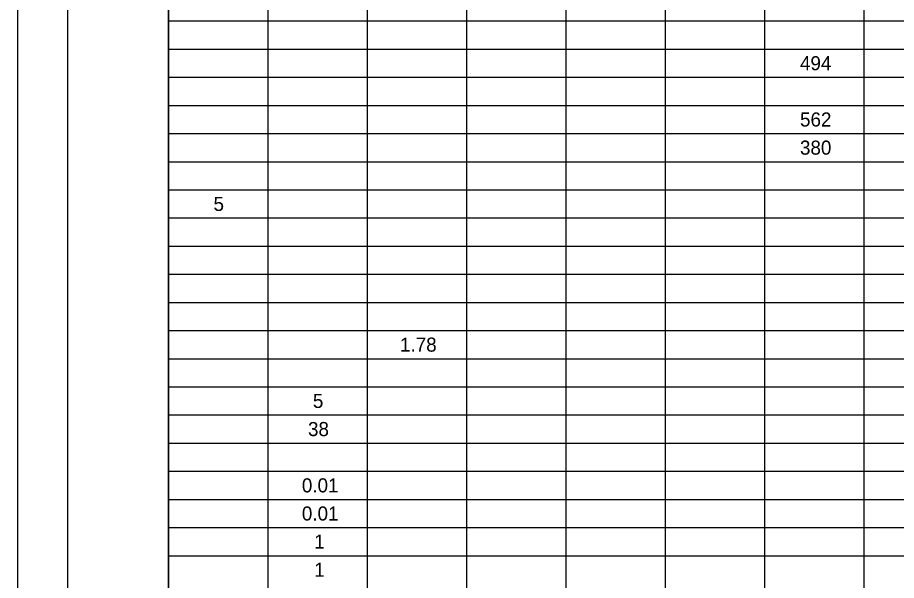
# Model space of a CAD drawing. Extents: x 0 to 34, y 0 to 22.
# Drawn here: x 0 to 8.74, y 10.89 to 16.49 of the extents above; entities that cross this region are included whole.
import ezdxf

# ---------------------------------------------------------------- set-up
doc = ezdxf.new("R2010")
doc.units = 0
for name, color, linetype in [('Default', 7, 'Continuous'), ('SH_Border', 7, 'Continuous'), ('SH_Cut_Line', 7, 'Continuous')]:
    doc.layers.add(name, color=color, linetype=linetype)

msp = doc.modelspace()

# ---------------------------------------------------------------- linework, layer by layer
at = {"layer": 'Default'}
for p, q in [((1.5, 21.5), (1.5, 0.50075)), ((2.4882, 20.94002), (2.4882, 0.50075)), ((3.4764, 20.94002), (3.4764, 0.50075)), ((4.4646, 20.94002), (4.4646, 0.50075)), ((5.4528, 20.94002), (5.4528, 0.50075)), ((6.441, 20.94002), (6.441, 0.50075)), ((7.4292, 20.94002), (7.4292, 0.50075)), ((8.4174, 20.94002), (8.4174, 0.50075)), ((1.5, 16.46018), (31.68951, 16.46018)), ((1.5, 16.18019), (31.68951, 16.18019)), ((1.5, 15.9002), (31.68951, 15.9002)), ((1.5, 15.62021), (31.68951, 15.62021)), ((1.5, 15.34022), (31.68951, 15.34022)), ((1.5, 15.06023), (31.68951, 15.06023)), ((1.5, 14.78024), (31.68951, 14.78024)), ((1.5, 14.50025), (31.68951, 14.50025)), ((1.5, 14.22026), (31.68951, 14.22026)), ((1.5, 13.94027), (31.68951, 13.94027)), ((1.5, 13.66028), (31.68951, 13.66028)), ((1.5, 13.38029), (31.68951, 13.38029)), ((1.5, 13.1003), (31.68951, 13.1003)), ((1.5, 12.82031), (31.68951, 12.82031)), ((1.5, 12.54032), (31.68951, 12.54032)), ((1.5, 12.26033), (31.68951, 12.26033)), ((1.5, 11.98034), (31.68951, 11.98034)), ((1.5, 11.70035), (31.68951, 11.70035)), ((1.5, 11.42036), (31.68951, 11.42036)), ((1.5, 11.14037), (31.68951, 11.14037))]:
    msp.add_line(p, q, dxfattribs=at)
at = {"layer": 'SH_Border'}
for points in [[(0.5, 21.5), (1.5, 21.5), (1.5, 0.5), (0.5, 0.5)], [(1.5, 21.5), (33.5, 21.5), (33.5, 0.5), (1.5, 0.5)]]:
    msp.add_lwpolyline(points, close=True, dxfattribs=at)
at = {"layer": 'SH_Cut_Line'}
msp.add_lwpolyline([(0, 0), (34, 0), (34, 22), (0, 22)], close=True, dxfattribs=at)

# ---------------------------------------------------------------- texts
at = {"layer": 'Default'}
for s, p in [('494', (7.780782, 15.970195)), ('562', (7.781166, 15.410215)), ('380', (7.780734, 15.130225)), ('5', (1.948675, 14.570245)), ('1.78', (3.803156, 13.170295)), ('5', (2.936875, 12.610315)), ('38', (2.888328, 12.330325)), ('0.01', (2.827249, 11.770345)), ('0.01', (2.827249, 11.490355)), ('1', (2.949552, 11.210365)), ('1', (2.949552, 10.930375))]:
    msp.add_text(s, height=0.14, dxfattribs=at).set_placement(p)

doc.saveas('drawing.dxf')
